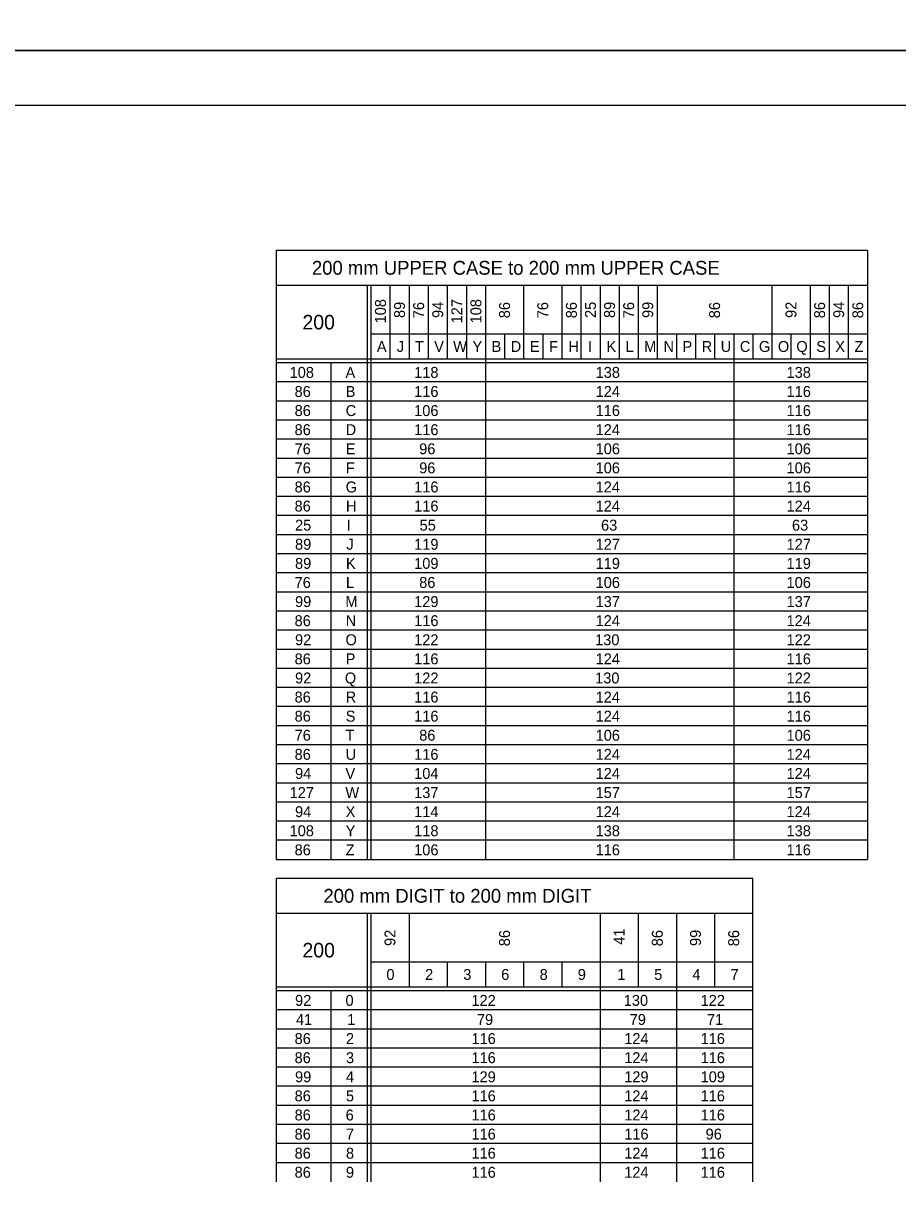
# Model space of a CAD drawing. Extents: x 637580 to 641849, y 297270 to 299646.
# Drawn here: x 638703.5 to 638943.9, y 298146.6 to 298465.1 of the extents above; entities that cross this region are included whole.
import ezdxf

# ---------------------------------------------------------------- set-up
doc = ezdxf.new("R2010")
doc.units = 0
for name, color, linetype in [('1', 7, 'Continuous'), ('2', 7, 'Continuous'), ('XCS-GRID-HVGL', 7, 'Continuous')]:
    doc.layers.add(name, color=color, linetype=linetype)

msp = doc.modelspace()

# ---------------------------------------------------------------- linework, layer by layer
at = {"layer": '1'}
msp.add_line((638461.31, 298442.63), (639247.31, 298442.63), dxfattribs=at)
at = {"layer": '2'}
for p, q in [((638935.56, 298402.63), (638773.06, 298402.63)), ((638773.06, 298402.63), (638773.06, 298235.25)), ((638935.56, 298402.63), (638935.56, 298235.25)), ((638773.06, 298393.13), (638935.56, 298393.13)), ((638798.06, 298393.13), (638798.06, 298235.25)), ((638799.06, 298393.13), (638799.06, 298235.25)), ((638804.31, 298393.13), (638804.31, 298372.75)), ((638809.56, 298393.13), (638809.56, 298372.75)), ((638814.81, 298393.13), (638814.81, 298372.75)), ((638820.06, 298393.13), (638820.06, 298372.75)), ((638825.31, 298393.13), (638825.31, 298372.75)), ((638830.56, 298393.13), (638830.56, 298235.25)), ((638841.06, 298393.13), (638841.06, 298372.75)), ((638851.56, 298393.13), (638851.56, 298372.75)), ((638856.81, 298393.13), (638856.81, 298372.75)), ((638862.06, 298393.13), (638862.06, 298372.75)), ((638867.31, 298393.13), (638867.31, 298372.75)), ((638872.56, 298393.13), (638872.56, 298372.75)), ((638877.81, 298393.13), (638877.81, 298372.75)), ((638909.31, 298393.13), (638909.31, 298372.75)), ((638919.81, 298393.13), (638919.81, 298372.75)), ((638925.06, 298393.13), (638925.06, 298372.75)), ((638930.31, 298393.13), (638930.31, 298372.75)), ((638799.06, 298379.75), (638935.56, 298379.75)), ((638835.81, 298379.75), (638835.81, 298372.75)), ((638846.31, 298379.75), (638846.31, 298372.75)), ((638883.06, 298379.75), (638883.06, 298372.75)), ((638888.31, 298379.75), (638888.31, 298372.75)), ((638893.56, 298379.75), (638893.56, 298372.75)), ((638893.56, 298379.75), (638893.56, 298372.75)), ((638898.81, 298379.75), (638898.81, 298235.25)), ((638904.06, 298379.75), (638904.06, 298372.75)), ((638914.56, 298379.75), (638914.56, 298372.75)), ((638935.56, 298372.75), (638773.06, 298372.75)), ((638935.56, 298371.75), (638773.06, 298371.75)), ((638788.06, 298371.75), (638788.06, 298235.25)), ((638935.56, 298366.5), (638773.06, 298366.5)), ((638935.56, 298361.25), (638773.06, 298361.25)), ((638935.56, 298356), (638773.06, 298356)), ((638935.56, 298350.75), (638773.06, 298350.75)), ((638935.56, 298345.5), (638773.06, 298345.5)), ((638935.56, 298340.25), (638773.06, 298340.25)), ((638935.56, 298335), (638773.06, 298335)), ((638935.56, 298329.75), (638773.06, 298329.75)), ((638935.56, 298324.5), (638773.06, 298324.5)), ((638935.56, 298319.25), (638773.06, 298319.25)), ((638935.56, 298314), (638773.06, 298314)), ((638935.56, 298308.75), (638773.06, 298308.75)), ((638935.56, 298303.5), (638773.06, 298303.5)), ((638935.56, 298298.25), (638773.06, 298298.25)), ((638935.56, 298293), (638773.06, 298293)), ((638935.56, 298287.75), (638773.06, 298287.75)), ((638935.56, 298282.5), (638773.06, 298282.5)), ((638935.56, 298277.25), (638773.06, 298277.25)), ((638935.56, 298272), (638773.06, 298272)), ((638935.56, 298266.75), (638773.06, 298266.75)), ((638935.56, 298261.5), (638773.06, 298261.5)), ((638935.56, 298256.25), (638773.06, 298256.25)), ((638935.56, 298251), (638773.06, 298251)), ((638935.56, 298245.75), (638773.06, 298245.75)), ((638935.56, 298240.5), (638773.06, 298240.5)), ((638773.06, 298235.25), (638773.06, 298235.25)), ((638773.06, 298235.25), (638935.56, 298235.25)), ((638904.06, 298230), (638773.06, 298230)), ((638773.06, 298230), (638773.06, 298146.63)), ((638904.06, 298146.63), (638904.06, 298230)), ((638773.06, 298220.5), (638904.06, 298220.5)), ((638798.06, 298220.5), (638798.06, 298146.63)), ((638799.06, 298220.5), (638799.06, 298146.63)), ((638809.56, 298220.5), (638809.56, 298200.13)), ((638862.06, 298220.5), (638862.06, 298146.63)), ((638872.56, 298220.5), (638872.56, 298200.13)), ((638883.06, 298220.5), (638883.06, 298146.63)), ((638893.56, 298220.5), (638893.56, 298200.13)), ((638799.06, 298207.13), (638904.06, 298207.13)), ((638820.06, 298207.13), (638820.06, 298200.13)), ((638830.56, 298207.13), (638830.56, 298200.13)), ((638841.06, 298207.13), (638841.06, 298200.13)), ((638851.56, 298207.13), (638851.56, 298200.13)), ((638904.06, 298200.13), (638773.06, 298200.13)), ((638904.06, 298199.13), (638773.06, 298199.13)), ((638788.06, 298199.13), (638788.06, 298146.63)), ((638904.06, 298193.88), (638773.06, 298193.88)), ((638904.06, 298188.63), (638773.06, 298188.63)), ((638904.06, 298183.38), (638773.06, 298183.38)), ((638904.06, 298178.13), (638773.06, 298178.13)), ((638904.06, 298172.88), (638773.06, 298172.88)), ((638904.06, 298167.63), (638773.06, 298167.63)), ((638904.06, 298162.38), (638773.06, 298162.38)), ((638904.06, 298157.13), (638773.06, 298157.13)), ((638904.06, 298151.88), (638773.06, 298151.88))]:
    msp.add_line(p, q, dxfattribs=at)
at = {"layer": 'XCS-GRID-HVGL'}
for points in [[(638421.31, 299051.63), (639262.31, 299051.63), (639262.31, 298457.63), (638421.31, 298457.63)], [(638421.31, 298457.63), (639262.31, 298457.63), (639262.31, 297863.63), (638421.31, 297863.63)]]:
    msp.add_lwpolyline(points, close=True, dxfattribs=at)

# ---------------------------------------------------------------- texts
at = {"layer": '2'}
for s, height, p in [('200 mm UPPER CASE to 200 mm UPPER CASE', 3.8, (638782.85, 298395.98)), ('200', 4, (638780.25, 298380.94)), ('A', 3, (638800.71, 298374.75)), ('J', 3, (638806.19, 298374.75)), ('T', 3, (638811.19, 298374.75)), ('V', 3, (638816.46, 298374.75)), ('W', 3, (638821.68, 298374.75)), ('Y', 3, (638826.99, 298374.75)), ('B', 3, (638832.25, 298374.75)), ('D', 3, (638837.5, 298374.75)), ('E', 3, (638842.77, 298374.75)), ('F', 3, (638848.07, 298374.75)), ('H', 3, (638853.34, 298374.75)), ('I', 3, (638858.75, 298374.75)), ('K', 3, (638863.84, 298374.75)), ('L', 3, (638869.09, 298374.75)), ('M', 3, (638874.18, 298374.75)), ('N', 3, (638879.5, 298374.75)), ('P', 3, (638884.75, 298374.75)), ('R', 3, (638890, 298374.75)), ('U', 3, (638895.24, 298374.75)), ('C', 3, (638900.5, 298374.75)), ('G', 3, (638905.75, 298374.75)), ('O', 3, (638910.96, 298374.75)), ('Q', 3, (638916.03, 298374.75)), ('S', 3, (638921.52, 298374.75)), ('X', 3, (638926.74, 298374.75)), ('Z', 3, (638932, 298374.75)), ('108', 3, (638776.71, 298367.63)), ('A', 3, (638792.08, 298367.63)), ('118', 3, (638810.96, 298367.63)), ('138', 3, (638860.84, 298367.63)), ('138', 3, (638913.34, 298367.63)), ('86', 3, (638778.09, 298362.38)), ('B', 3, (638792.13, 298362.38)), ('116', 3, (638810.96, 298362.38)), ('124', 3, (638860.84, 298362.38)), ('116', 3, (638913.34, 298362.38)), ('86', 3, (638778.09, 298357.13)), ('C', 3, (638792.13, 298357.13)), ('106', 3, (638810.96, 298357.13)), ('116', 3, (638860.84, 298357.13)), ('116', 3, (638913.34, 298357.13)), ('86', 3, (638778.09, 298351.88)), ('D', 3, (638792.13, 298351.88)), ('116', 3, (638810.96, 298351.88)), ('124', 3, (638860.84, 298351.88)), ('116', 3, (638913.34, 298351.88)), ('76', 3, (638778.09, 298346.63)), ('E', 3, (638792.14, 298346.63)), ('96', 3, (638812.34, 298346.63)), ('106', 3, (638860.84, 298346.63)), ('106', 3, (638913.34, 298346.63)), ('76', 3, (638778.09, 298341.38)), ('F', 3, (638792.2, 298341.38)), ('96', 3, (638812.34, 298341.38)), ('106', 3, (638860.84, 298341.38)), ('106', 3, (638913.34, 298341.38)), ('86', 3, (638778.09, 298336.13)), ('G', 3, (638792.13, 298336.13)), ('116', 3, (638810.96, 298336.13)), ('124', 3, (638860.84, 298336.13)), ('116', 3, (638913.34, 298336.13)), ('86', 3, (638778.09, 298330.88)), ('H', 3, (638792.21, 298330.88)), ('116', 3, (638810.96, 298330.88)), ('124', 3, (638860.84, 298330.88)), ('124', 3, (638913.34, 298330.88)), ('25', 3, (638778.21, 298325.63)), ('I', 3, (638792.38, 298325.63)), ('55', 3, (638812.46, 298325.63)), ('63', 3, (638862.34, 298325.63)), ('63', 3, (638914.84, 298325.63)), ('89', 3, (638778.21, 298320.38)), ('J', 3, (638792.32, 298320.38)), ('119', 3, (638810.96, 298320.38)), ('127', 3, (638860.84, 298320.38)), ('127', 3, (638913.34, 298320.38)), ('89', 3, (638778.21, 298315.13)), ('K', 3, (638792.21, 298315.13)), ('109', 3, (638810.96, 298315.13)), ('119', 3, (638860.84, 298315.13)), ('119', 3, (638913.34, 298315.13)), ('76', 3, (638778.09, 298309.88)), ('L', 3, (638792.21, 298309.88)), ('86', 3, (638812.34, 298309.88)), ('106', 3, (638860.84, 298309.88)), ('106', 3, (638913.34, 298309.88)), ('99', 3, (638778.21, 298304.63)), ('M', 3, (638792.06, 298304.63)), ('129', 3, (638810.96, 298304.63)), ('137', 3, (638860.84, 298304.63)), ('137', 3, (638913.34, 298304.63)), ('86', 3, (638778.09, 298299.38)), ('N', 3, (638792.13, 298299.38)), ('116', 3, (638810.96, 298299.38)), ('124', 3, (638860.84, 298299.38)), ('124', 3, (638913.34, 298299.38)), ('92', 3, (638778.21, 298294.13)), ('O', 3, (638792.08, 298294.13)), ('122', 3, (638810.96, 298294.13)), ('130', 3, (638860.71, 298294.13)), ('122', 3, (638913.34, 298294.13)), ('86', 3, (638778.09, 298288.88)), ('P', 3, (638792.13, 298288.88)), ('116', 3, (638810.96, 298288.88)), ('124', 3, (638860.84, 298288.88)), ('116', 3, (638913.34, 298288.88)), ('92', 3, (638778.21, 298283.63)), ('Q', 3, (638791.9, 298283.63)), ('122', 3, (638810.96, 298283.63)), ('130', 3, (638860.71, 298283.63)), ('122', 3, (638913.34, 298283.63)), ('86', 3, (638778.09, 298278.38)), ('R', 3, (638792.13, 298278.38)), ('116', 3, (638810.96, 298278.38)), ('124', 3, (638860.84, 298278.38)), ('116', 3, (638913.34, 298278.38)), ('86', 3, (638778.09, 298273.13)), ('S', 3, (638792.14, 298273.13)), ('116', 3, (638810.96, 298273.13)), ('124', 3, (638860.84, 298273.13)), ('116', 3, (638913.34, 298273.13)), ('76', 3, (638778.09, 298267.88)), ('T', 3, (638792.07, 298267.88)), ('86', 3, (638812.34, 298267.88)), ('106', 3, (638860.84, 298267.88)), ('106', 3, (638913.34, 298267.88)), ('86', 3, (638778.09, 298262.63)), ('U', 3, (638792.12, 298262.63)), ('116', 3, (638810.96, 298262.63)), ('124', 3, (638860.84, 298262.63)), ('124', 3, (638913.34, 298262.63)), ('94', 3, (638778.21, 298257.38)), ('V', 3, (638792.08, 298257.38)), ('104', 3, (638810.96, 298257.38)), ('124', 3, (638860.84, 298257.38)), ('124', 3, (638913.34, 298257.38)), ('127', 3, (638776.71, 298252.13)), ('W', 3, (638792.06, 298252.13)), ('137', 3, (638810.96, 298252.13)), ('157', 3, (638860.84, 298252.13)), ('157', 3, (638913.34, 298252.13)), ('94', 3, (638778.21, 298246.88)), ('X', 3, (638792.12, 298246.88)), ('114', 3, (638810.96, 298246.88)), ('124', 3, (638860.84, 298246.88)), ('124', 3, (638913.34, 298246.88)), ('108', 3, (638776.71, 298241.63)), ('Y', 3, (638792.12, 298241.63)), ('118', 3, (638810.96, 298241.63)), ('138', 3, (638860.84, 298241.63)), ('138', 3, (638913.34, 298241.63)), ('86', 3, (638778.09, 298236.38)), ('Z', 3, (638792.13, 298236.38)), ('106', 3, (638810.96, 298236.38)), ('116', 3, (638860.84, 298236.38)), ('116', 3, (638913.34, 298236.38)), ('200 mm DIGIT to 200 mm DIGIT', 3.8, (638786.01, 298223.35)), ('200', 4, (638780.25, 298208.31)), ('0', 3, (638803.33, 298202.13)), ('2', 3, (638813.96, 298202.13)), ('3', 3, (638824.46, 298202.13)), ('6', 3, (638834.88, 298202.13)), ('8', 3, (638845.46, 298202.13)), ('9', 3, (638855.95, 298202.13)), ('1', 3, (638866.8, 298202.13)), ('5', 3, (638876.96, 298202.13)), ('4', 3, (638887.46, 298202.13)), ('7', 3, (638897.96, 298202.13)), ('92', 3, (638778.21, 298195)), ('0', 3, (638792.08, 298195)), ('122', 3, (638826.71, 298195)), ('130', 3, (638868.58, 298195)), ('122', 3, (638889.71, 298195)), ('41', 3, (638778.46, 298189.75)), ('1', 3, (638792.55, 298189.75)), ('79', 3, (638828.21, 298189.75)), ('79', 3, (638870.21, 298189.75)), ('71', 3, (638891.46, 298189.75)), ('86', 3, (638778.09, 298184.5)), ('2', 3, (638792.21, 298184.5)), ('116', 3, (638826.71, 298184.5)), ('124', 3, (638868.71, 298184.5)), ('116', 3, (638889.71, 298184.5)), ('86', 3, (638778.09, 298179.25)), ('3', 3, (638792.21, 298179.25)), ('116', 3, (638826.71, 298179.25)), ('124', 3, (638868.71, 298179.25)), ('116', 3, (638889.71, 298179.25)), ('99', 3, (638778.21, 298174)), ('4', 3, (638792.21, 298174)), ('129', 3, (638826.71, 298174)), ('129', 3, (638868.71, 298174)), ('109', 3, (638889.71, 298174)), ('86', 3, (638778.09, 298168.75)), ('5', 3, (638792.21, 298168.75)), ('116', 3, (638826.71, 298168.75)), ('124', 3, (638868.71, 298168.75)), ('116', 3, (638889.71, 298168.75)), ('86', 3, (638778.09, 298163.5)), ('6', 3, (638792.13, 298163.5)), ('116', 3, (638826.71, 298163.5)), ('124', 3, (638868.71, 298163.5)), ('116', 3, (638889.71, 298163.5)), ('86', 3, (638778.09, 298158.25)), ('7', 3, (638792.21, 298158.25)), ('116', 3, (638826.71, 298158.25)), ('116', 3, (638868.71, 298158.25)), ('96', 3, (638891.09, 298158.25)), ('86', 3, (638778.09, 298153)), ('8', 3, (638792.21, 298153)), ('116', 3, (638826.71, 298153)), ('124', 3, (638868.71, 298153)), ('116', 3, (638889.71, 298153)), ('86', 3, (638778.09, 298147.75)), ('9', 3, (638792.2, 298147.75)), ('116', 3, (638826.71, 298147.75)), ('124', 3, (638868.71, 298147.75)), ('116', 3, (638889.71, 298147.75))]:
    msp.add_text(s, height=height, dxfattribs=at).set_placement(p)
for s, p in [('108', (638803.19, 298382.59)), ('89', (638808.44, 298384.08)), ('76', (638813.69, 298384.01)), ('94', (638818.94, 298384.09)), ('127', (638824.19, 298382.59)), ('108', (638829.44, 298382.59)), ('86', (638837.31, 298384.01)), ('76', (638847.81, 298384.01)), ('86', (638855.69, 298384.01)), ('25', (638860.94, 298384.09)), ('89', (638866.19, 298384.08)), ('76', (638871.44, 298384.01)), ('99', (638876.69, 298384.08)), ('86', (638895.06, 298384.01)), ('92', (638916.06, 298384.09)), ('86', (638923.94, 298384.01)), ('94', (638929.19, 298384.09)), ('86', (638934.44, 298384.01)), ('92', (638805.81, 298211.46)), ('86', (638837.31, 298211.38)), ('41', (638868.81, 298211.81)), ('86', (638879.31, 298211.38)), ('99', (638889.81, 298211.45)), ('86', (638900.31, 298211.38))]:
    msp.add_text(s, height=3, rotation=90, dxfattribs=at).set_placement(p)

doc.saveas('drawing.dxf')
